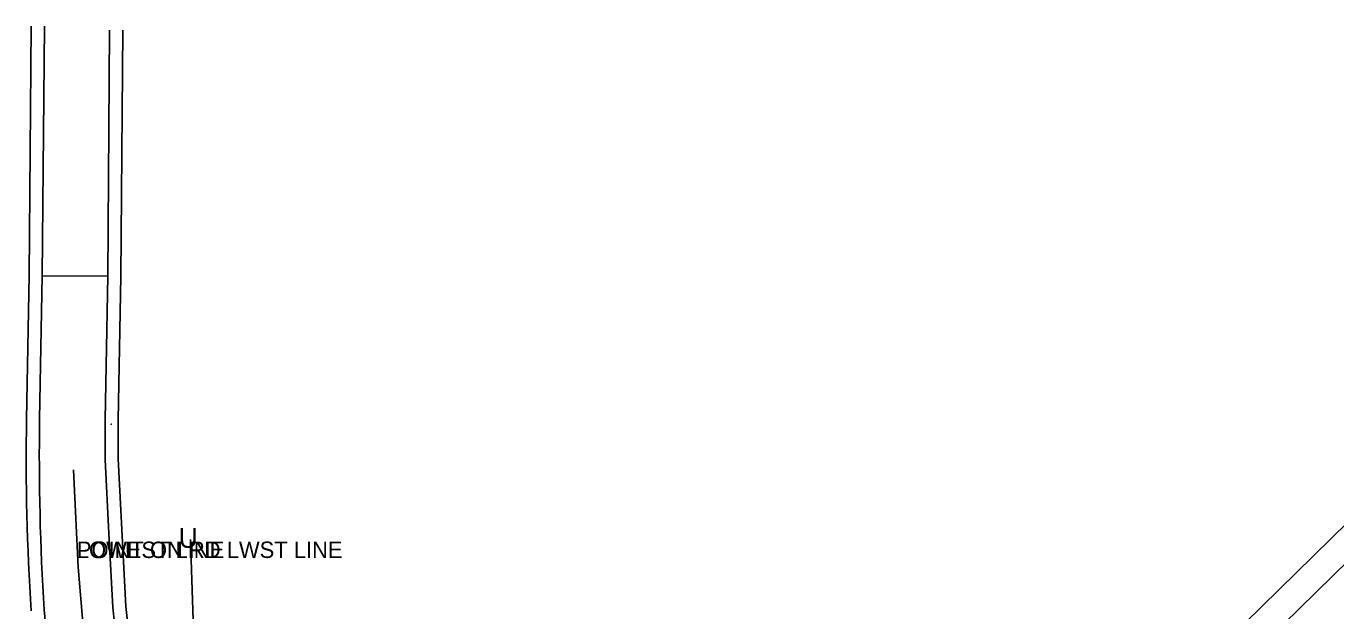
# Model space of a CAD drawing. Extents: x 1282810 to 1284464, y 402460 to 405899.
# Drawn here: x 1283659.3 to 1284058.4, y 404863.5 to 405041.7 of the extents above; entities that cross this region are included whole.
import ezdxf

# ---------------------------------------------------------------- set-up
doc = ezdxf.new("R2010")
doc.units = 0
for name, color, linetype in [('Default', 7, 'Continuous'), ('MOT_Proposed Road_Stage 2', 7, 'Continuous'), ('MOT_Shld_Stage 2', 7, 'Continuous'), ('S_EDGE_PAVEMENT', 7, 'Continuous'), ('S_ELECTRIC_UTILITIES_ANNOT', 7, 'Continuous'), ('S_MSC_PT_SYM', 7, 'Continuous'), ('S_PAVEMENT_CROWN', 7, 'Continuous'), ('S_SHOULDER', 7, 'Continuous'), ('S_SURVEY_TEXT_ANNOT', 7, 'Continuous'), ('S_UNDERGROUND_CABLE', 7, 'Continuous'), ('S_UTL_PT_SYM', 7, 'Continuous')]:
    doc.layers.add(name, color=color, linetype=linetype)

msp = doc.modelspace()

# ---------------------------------------------------------------- linework, layer by layer
at = {"layer": 'MOT_Proposed Road_Stage 2'}
for q in [(1283663.4, 404921.92), (1283684.16, 404965.5)]:
    msp.add_line((1283664.16, 404965.64), q, dxfattribs=at)
for points in [[(1283683.36, 404909.58), (1283683.32, 404921.78), (1283684.16, 404965.5)], [(1283683.36, 404909.58), (1283684.52, 404887.05), (1283685.68, 404864.53), (1283688.07, 404842.56), (1283690.46, 404820.59), (1283695.16, 404797.49), (1283699.85, 404774.39), (1283705.86, 404754.34), (1283711.86, 404734.29), (1283717.93, 404717.85), (1283724, 404701.42), (1283734.19, 404680.26), (1283747.72, 404660.7), (1283757.62, 404653.05), (1283767.51, 404645.4), (1283780.09, 404642.18), (1283792.68, 404638.97), (1283809.12, 404640.98), (1283825.72, 404649.39), (1283836.19, 404657.81), (1283846.65, 404666.23)]]:
    msp.add_lwpolyline(points, dxfattribs=at)
for centre, radius, start, end in [((1284368.45, 404909.96), 705.15, 179.02775, 183.75514), ((1284368.31, 404916.78), 705.49, 184.30872, 189.89583)]:
    msp.add_arc(centre, radius, start, end, dxfattribs=at)
at = {"layer": 'MOT_Shld_Stage 2'}
msp.add_line((1283660.16, 404965.67), (1283659.4, 404921.95), dxfattribs=at)
msp.add_arc((1284368.45, 404909.96), 709.15, 179.02775, 183.75514, dxfattribs=at)
at = {"layer": 'S_EDGE_PAVEMENT'}
msp.add_line((1283941.7, 404760.75), (1284151.8, 404966.56), dxfattribs=at)
for points in [[(1283664.16, 404965.64), (1283664.85, 405041.69)], [(1283684.16, 404965.5), (1283684.73, 405040.5)], [(1283683.36, 404909.58), (1283684.52, 404887.05), (1283685.68, 404864.53), (1283688.07, 404842.56), (1283690.46, 404820.59), (1283695.16, 404797.49), (1283699.85, 404774.39), (1283705.86, 404754.34), (1283711.86, 404734.29), (1283717.93, 404717.85), (1283724, 404701.42), (1283734.19, 404680.26), (1283747.72, 404660.7), (1283757.62, 404653.05), (1283767.51, 404645.4), (1283780.09, 404642.18), (1283792.68, 404638.97), (1283809.12, 404640.98), (1283825.72, 404649.39), (1283836.19, 404657.81), (1283846.65, 404666.23)]]:
    msp.add_lwpolyline(points, dxfattribs=at)
at = {"layer": 'S_MSC_PT_SYM'}
msp.add_lwpolyline([(1283674.73, 404884.6), (1283674.73, 404884.65), (1283674.73, 404884.6), (1283674.68, 404884.6), (1283674.73, 404884.6), (1283674.73, 404884.55), (1283674.73, 404884.6), (1283674.78, 404884.6)], dxfattribs=at)
at = {"layer": 'S_PAVEMENT_CROWN'}
msp.add_lwpolyline([(1283763.06, 404581.02), (1283757.18, 404587.96), (1283744.84, 404602.59), (1283735.46, 404615.11), (1283727.38, 404629.8), (1283720.71, 404648.55), (1283716.16, 404664.6), (1283711.6, 404680.66), (1283706.63, 404699.87), (1283701.66, 404719.08), (1283696.55, 404740.81), (1283691.44, 404762.55), (1283688.17, 404778.09), (1283684.91, 404793.63), (1283681.52, 404817.08), (1283678.14, 404840.54), (1283676.65, 404858.67), (1283675.16, 404876.81), (1283674.46, 404891.63), (1283673.76, 404906.45)], dxfattribs=at)
at = {"layer": 'S_SHOULDER'}
msp.add_line((1283916.97, 404748.07), (1284145.73, 404972.68), dxfattribs=at)
for points in [[(1283660.16, 404965.67), (1283660.85, 405041.72)], [(1283687.36, 404909.59), (1283687.32, 404921.74), (1283688.15, 404965.44), (1283688.73, 405040.47)], [(1283687.35, 404909.78), (1283689.67, 404864.85), (1283694.42, 404821.2), (1283697.76, 404804.78)]]:
    msp.add_lwpolyline(points, dxfattribs=at)
at = {"layer": 'S_UNDERGROUND_CABLE'}
msp.add_line((1283711.08, 404830.54), (1283709.4, 404885.24), dxfattribs=at)
at = {"layer": 'S_UTL_PT_SYM'}
for points in [[(1283685.22, 404920.39), (1283685.22, 404920.44), (1283685.22, 404920.39), (1283685.17, 404920.39), (1283685.22, 404920.39), (1283685.22, 404920.34), (1283685.22, 404920.39), (1283685.27, 404920.39)], [(1283674.73, 404884.59), (1283674.73, 404884.64), (1283674.73, 404884.59), (1283674.68, 404884.59), (1283674.73, 404884.59), (1283674.73, 404884.54), (1283674.73, 404884.59), (1283674.78, 404884.59)]]:
    msp.add_lwpolyline(points, dxfattribs=at)

# ---------------------------------------------------------------- texts
at = {"layer": 'Default'}
msp.add_text('U', height=6, rotation=360, dxfattribs=at).set_placement((1283705.77, 404882.7))
at = {"layer": 'S_ELECTRIC_UTILITIES_ANNOT'}
msp.add_text('LOWEST LINE', height=5, dxfattribs=at).set_placement((1283674.73, 404879.59))
at = {"layer": 'S_SURVEY_TEXT_ANNOT'}
msp.add_text('POINT ON RD LWST LINE', height=5, dxfattribs=at).set_placement((1283674.73, 404879.6))

doc.saveas('drawing.dxf')
